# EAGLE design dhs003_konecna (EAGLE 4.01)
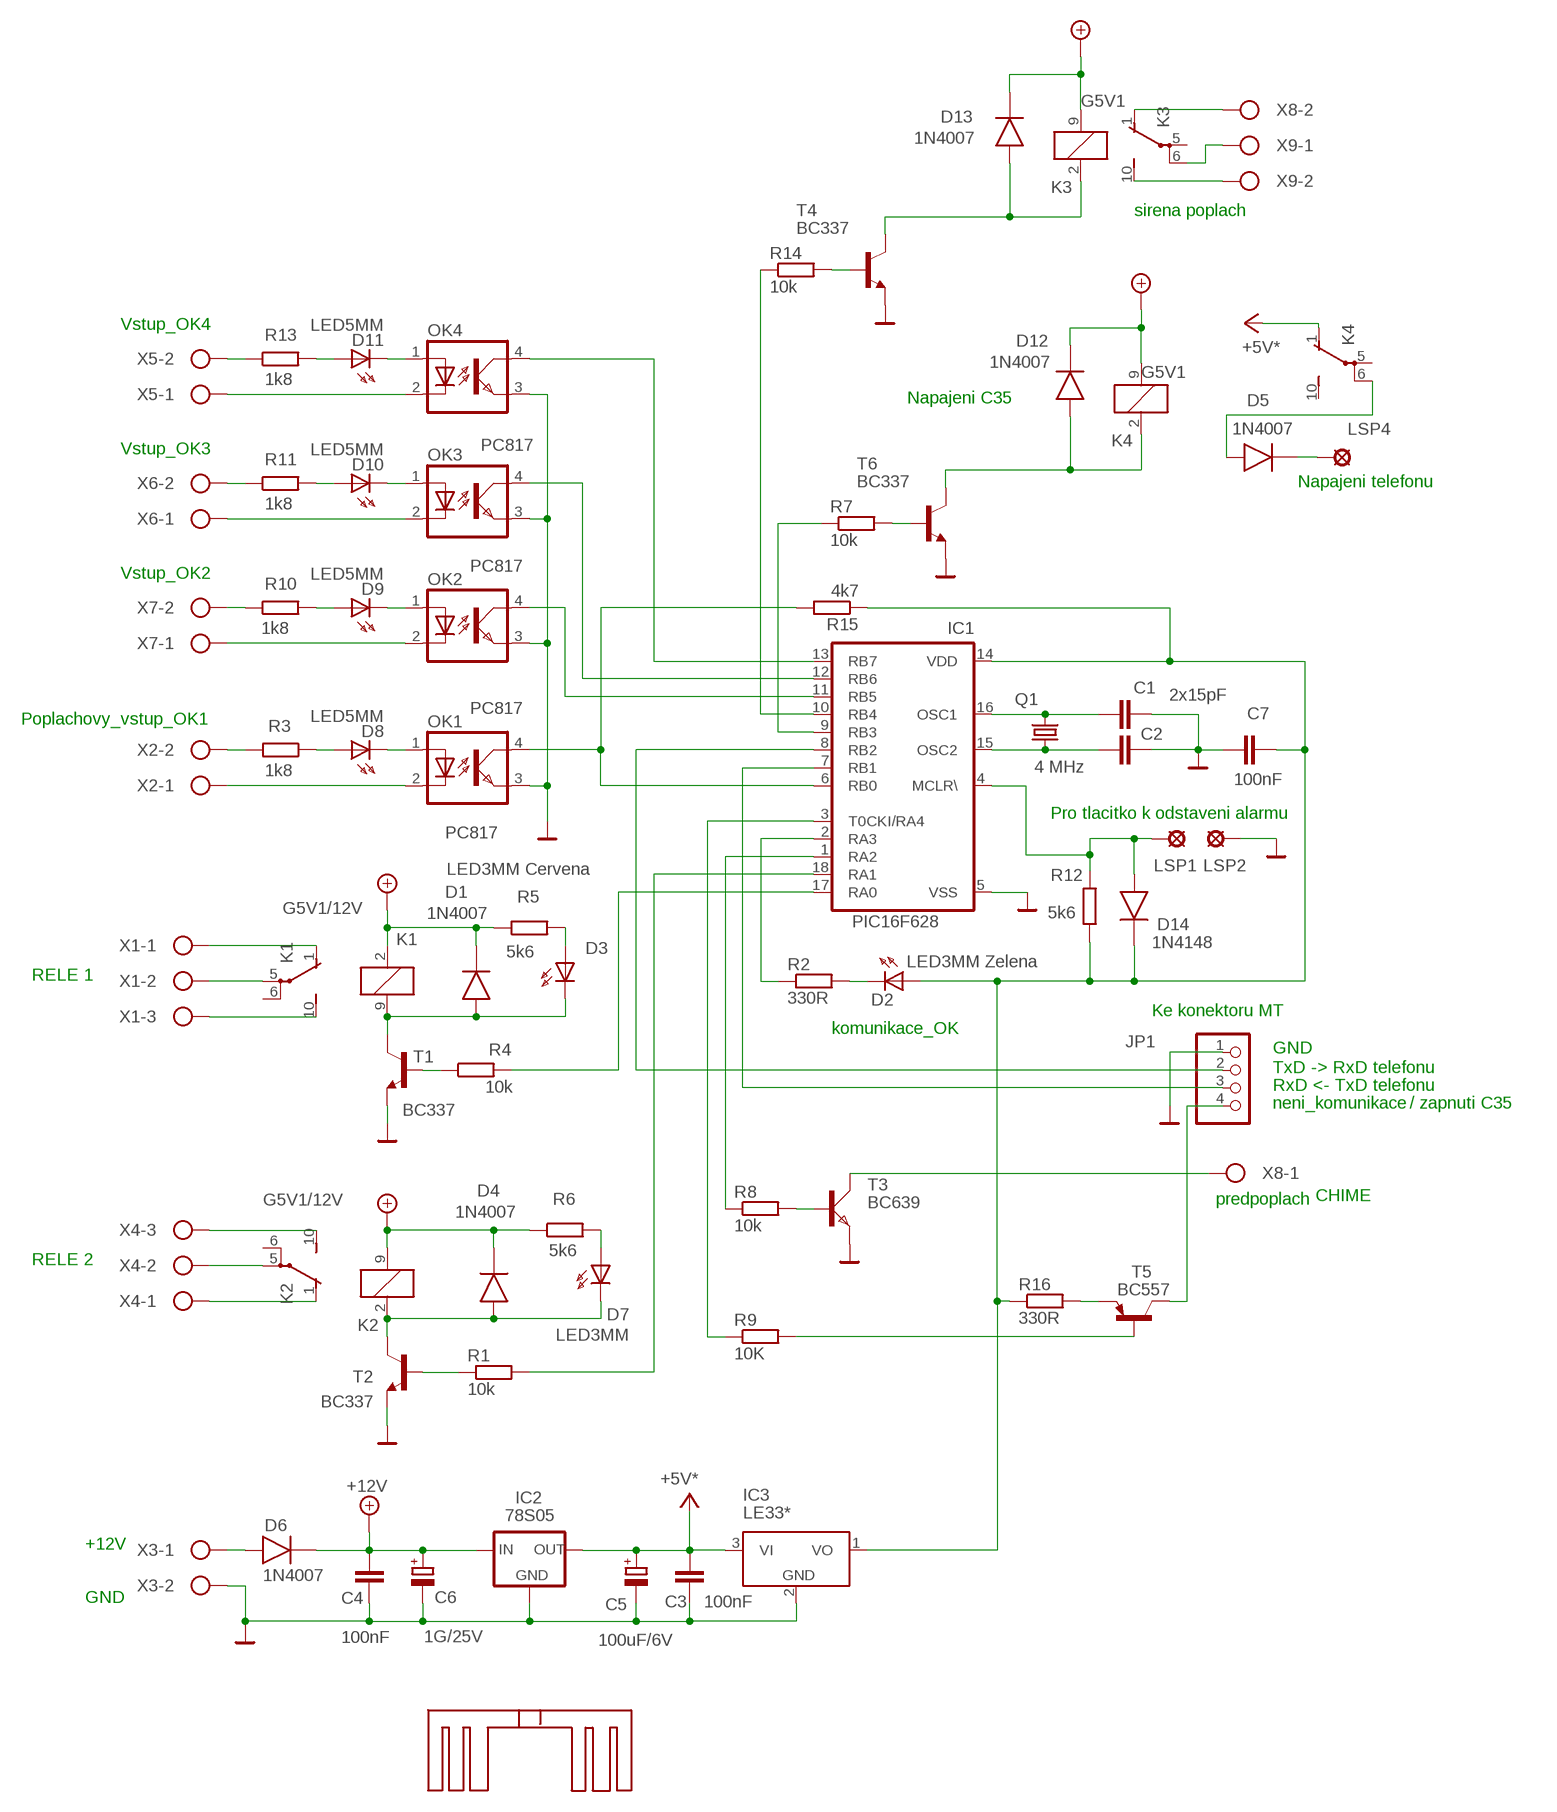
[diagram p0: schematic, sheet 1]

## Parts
C1  2x15pF  C-EU025-025X050  [C025-025X050]
C2  C-EU025-025X050  [C025-025X050]
C3  100nF  C-EU025-025X050  [C025-025X050]
C4  100nF  C-EU025-025X050  [C025-025X050]
C5  100uF/6V  CPOL-EUE2.5-7  [E2,5-7]
C6  1G/25V  CPOL-EUE5-13  [E5-13]
C7  100nF  C-EU025-025X050  [C025-025X050]
D1  1N4007  [DO41]
D2  LED3MM Zelena  LED3MM  [LED3MM]
D3  LED3MM Cervena  LED3MM  [LED3MM]
D4  1N4007  [DO41]
D5  1N4007  [DO41]
D6  1N4007  [DO41]
D7  LED3MM  [LED3MM]
D8  LED5MM  [LED5MM]
D9  LED5MM  [LED5MM]
D10  LED5MM  [LED5MM]
D11  LED5MM  [LED5MM]
D12  1N4007  [DO41]
D13  1N4007  [DO41]
D14  1N4148  [DO41]
IC1  PIC16F628  PIC16F84AP  [DIL18]
IC2  78S05  78XXS  [78XXS]
IC3  LE33*  [TO92]
JP1  PINHD-1X4  [1X04]
K1  G5V1/12V  G5V1  [G5V1]
K2  G5V1/12V  G5V1  [G5V1]
K3  G5V1  [G5V1]
K4  G5V1  [G5V1]
LSP1  LSP10  [LSP10]
LSP2  LSP10  [LSP10]
LSP4  LSP10  [LSP10]
OK1  PC817  [DIL04]
OK2  PC817  [DIL04]
OK3  PC817  [DIL04]
OK4  PC817  [DIL04]
Q1  4 MHz  HC49U-V  [HC49U-V]
R1  10k  R-EU_0207/10  [0207/10]
R2  330R  R-EU_0207/10  [0207/10]
R3  1k8  R-EU_0207/10  [0207/10]
R4  10k  R-EU_0207/10  [0207/10]
R5  5k6  R-EU_0207/10  [0207/10]
R6  5k6  R-EU_0207/10  [0207/10]
R7  10k  R-EU_0207/10  [0207/10]
R8  10k  R-EU_0207/10  [0207/10]
R9  10K  R-EU_0207/10  [0207/10]
R10  1k8  R-EU_0207/10  [0207/10]
R11  1k8  R-EU_0207/10  [0207/10]
R12  5k6  R-EU_0207/10  [0207/10]
R13  1k8  R-EU_0207/10  [0207/10]
R14  10k  R-EU_0207/10  [0207/10]
R15  4k7  R-EU_0207/10  [0207/10]
R16  330R  R-EU_0207/10  [0207/10]
RADIATOR1  V4330N*  [V4330N]
T1  BC337  [TO92]
T2  BC337  [TO92]
T3  BC639  [SOT54D]
T4  BC337  [TO92]
T5  BC557  [TO92]
T6  BC337  [TO92]
X1  AK500/3  [AK500/3]
X2  AK500/2  [AK500/2]
X3  AK500/2  [AK500/2]
X4  AK500/3  [AK500/3]
X5  AK500/2  [AK500/2]
X6  AK500/2  [AK500/2]
X7  AK500/2  [AK500/2]
X8  AK500/2  [AK500/2]
X9  AK500/2  [AK500/2]

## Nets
0V: C1.1 C2.1 C3.1 C4.1 C5.- C6.- C7.1 IC1.5(VSS) IC2.GND IC3.2(GND) JP1.1 LSP2.MP OK1.3(EMIT) OK2.3(EMIT) OK3.3(EMIT) OK4.3(EMIT) T1.1(E) T2.1(E) T3.E T4.1(E) T6.1(E) X3.2
+5V: C3.2 C5.+ IC2.OUT IC3.3(VI) K4.1(2:O) ; supply symbol labelled +5V*
+12V: C4.2 C6.+ D1.K D4.K D6.K D12.K D13.K IC2.IN K1.2 K2.9 K3.9 K4.9 R5.1 R6.1
N$1: C1.2 IC1.16(OSC1) Q1.2
N$2: C2.2 IC1.15(OSC2) Q1.1
N$3: R3.2 X2.2
N$4: OK1.2(C) X2.1
N$5: IC1.9(RB3) R7.1
N$6: K1.5(2:P) X1.2
N$7: K1.1(2:O) X1.1
N$8: IC1.17(RA0) R4.2
N$9: IC1.6(RB0) OK1.4(COL) R15.2
N$10: D4.A D7.K(C) K2.2 T2.3(C)
N$11: K2.10(2:S) X4.3
N$12: R1.1 T2.2(B)
N$13: D14.A IC1.4(MCLR\) LSP1.MP R12.2
N$14: OK2.2(C) X7.1
N$15: C7.2 D2.A D14.K IC1.14(VDD) IC3.1(VO) R12.1 R15.1 R16.1
N$16: K1.10(2:S) X1.3
N$17: IC1.2(RA3) R2.1
N$18: D2.K(C) R2.2
N$19: D1.A D3.K(C) K1.9 T1.3(C)
N$20: K2.5(2:P) X4.2
N$21: D6.A X3.1
N$22: D7.A R6.2
N$23: D3.A R5.2
N$24: R10.1 X7.2
N$25: R4.1 T1.2(B)
N$26: IC1.7(RB1) JP1.3
N$27: IC1.8(RB2) JP1.2
N$28: R11.1 X6.2
N$29: IC1.18(RA1) R1.2
N$30: K2.1(2:O) X4.1
N$31: JP1.4 T5.3(C)
N$32: IC1.1(RA2) R8.1
N$33: OK3.2(C) X6.1
N$34: D11.A R13.2
N$35: D11.K(C) OK4.1(A)
N$36: D10.A R11.2
N$37: D10.K(C) OK3.1(A)
N$38: IC1.11(RB5) OK2.4(COL)
N$39: IC1.12(RB6) OK3.4(COL)
N$40: D9.A R10.2
N$41: D9.K(C) OK2.1(A)
N$42: D8.A R3.1
N$43: OK4.2(C) X5.1
N$44: R13.1 X5.2
N$45: R8.2 T3.B
N$46: D8.K(C) OK1.1(A)
N$47: D5.K LSP4.MP
N$48: T3.C X8.1
N$49: IC1.13(RB7) OK4.4(COL)
N$50: IC1.3(T0CKI/RA4) R9.1
N$51: IC1.10(RB4) R14.1
N$52: R9.2 T5.2(B)
N$53: R14.2 T4.2(B)
N$54: D13.A K3.2 T4.3(C)
N$55: K3.6(2:P) X9.1
N$56: K3.1(2:O) X8.2
N$57: K3.10(2:S) X9.2
N$58: R16.2 T5.1(E)
N$59: D5.A K4.6(2:P)
N$61: R7.2 T6.2(B)
N$62: D12.A K4.2 T6.3(C)
Unconnected: K1.6(2:P) K2.6(2:P) K3.5(2:P) K4.5(2:P) K4.10(2:S)

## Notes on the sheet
- sirena poplach
- Vstup_OK4
- Napajeni C35
- Vstup_OK3
- Napajeni telefonu
- Vstup_OK2
- Poplachovy_vstup_OK1
- Pro tlacitko k odstaveni alarmu
- RELE 1
- Ke konektoru MT
- komunikace_OK
- GND
- TxD -> RxD telefonu
- RxD <- TxD telefonu
- neni_komunikace | / zapnuti C35
- predpoplach | CHIME
- RELE 2
- +12V
- GND

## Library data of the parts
C1-C4 C7 = rcl:C-EU: CAPACITOR, European symbol
C5 C6 = rcl:CPOL-EU: POLARIZED CAPACITOR, European symbol
D1 D4-D6 D12 D13 = GM99:1N4007
D2 D3 D7 = led:LED3MM: LED
D8-D11 = led:LED5MM: LED
D14 = GM99:1N4148
IC1 = microchip:PIC16F8*: MICROCONTROLLER 8-Bit PIC16F8X Family - CMOS Flash/EEPROM Pin Compatible : PIC16F83, PIC16CR83, PIC16F84A, PIC16CR84 see also PIC16C*
IC2 = v-reg:78XXS: VOLTAGE REGULATOR
IC3 = DH_servis:LE33
JP1 = pinhead:PINHD-1X4: PIN HEADER
K1-K4 = relay:G5V1: RELAY 1 x switch, 0.5 A/125 V AC, 1 A/24 V DC , Omron
LSP1 LSP2 LSP4 = solpad:LSP10: SOLDER PAD
OK1-OK4 = optocoupler:PC817: SHARP OPTO COUPLER
Q1 = crystal:HC49U-V: CRYSTAL
R1-R16 = rcl:R-EU_: RESISTOR, European symbol
RADIATOR1 = DH_servis:V4330N
T1 T2 T4 T6 = transistor-npn:BC337: NPN TRANSISTOR
T3 = transistor-small-signal:BC639: NPN TRANSISTOR
T5 = transistor-pnp:BC557: PNP TRANSISTOR
X1 X4 = con-ptr500:AK500/3: CONNECTOR
X2 X3 X5-X9 = con-ptr500:AK500/2: CONNECTOR

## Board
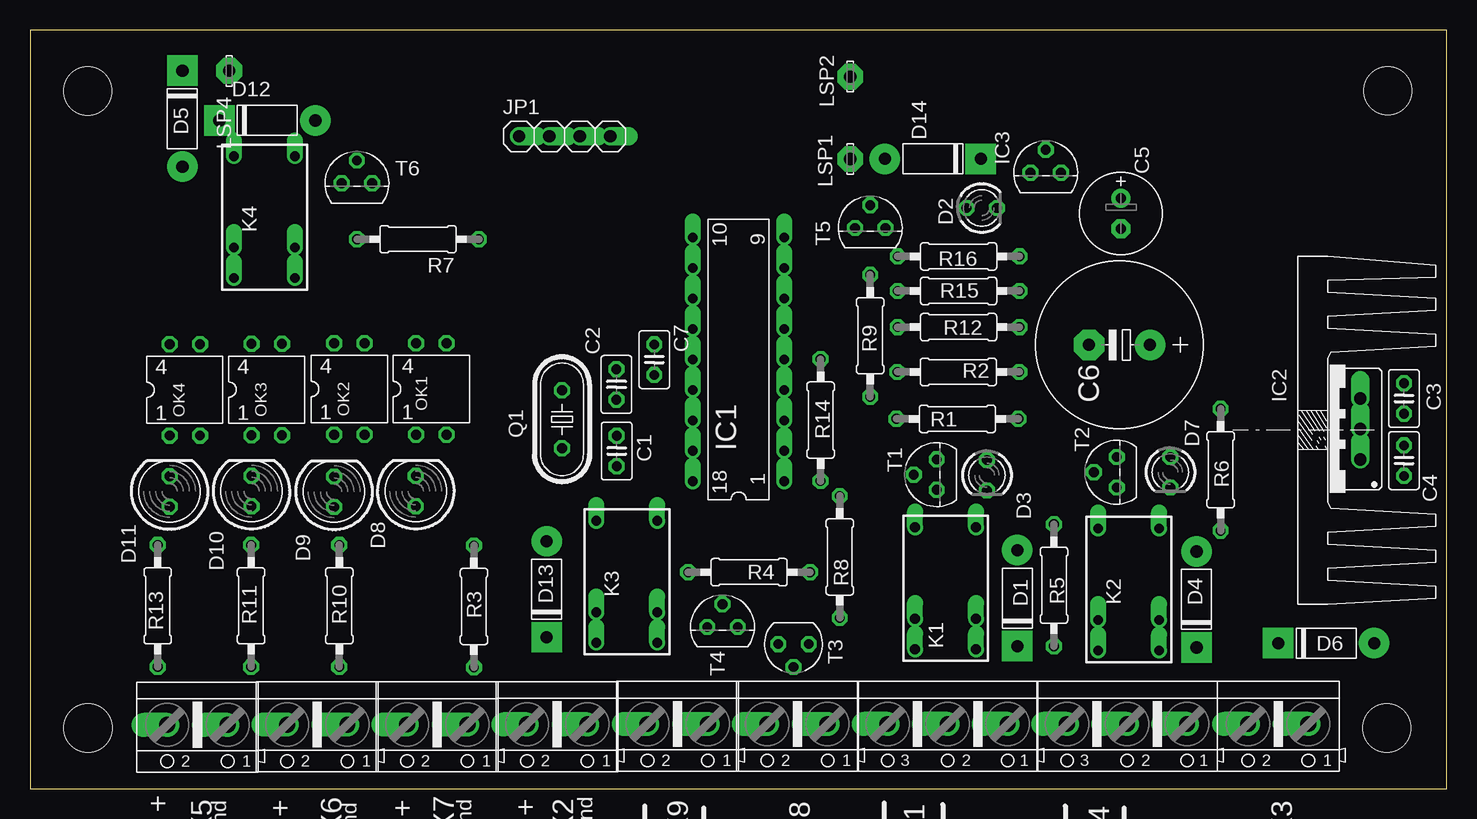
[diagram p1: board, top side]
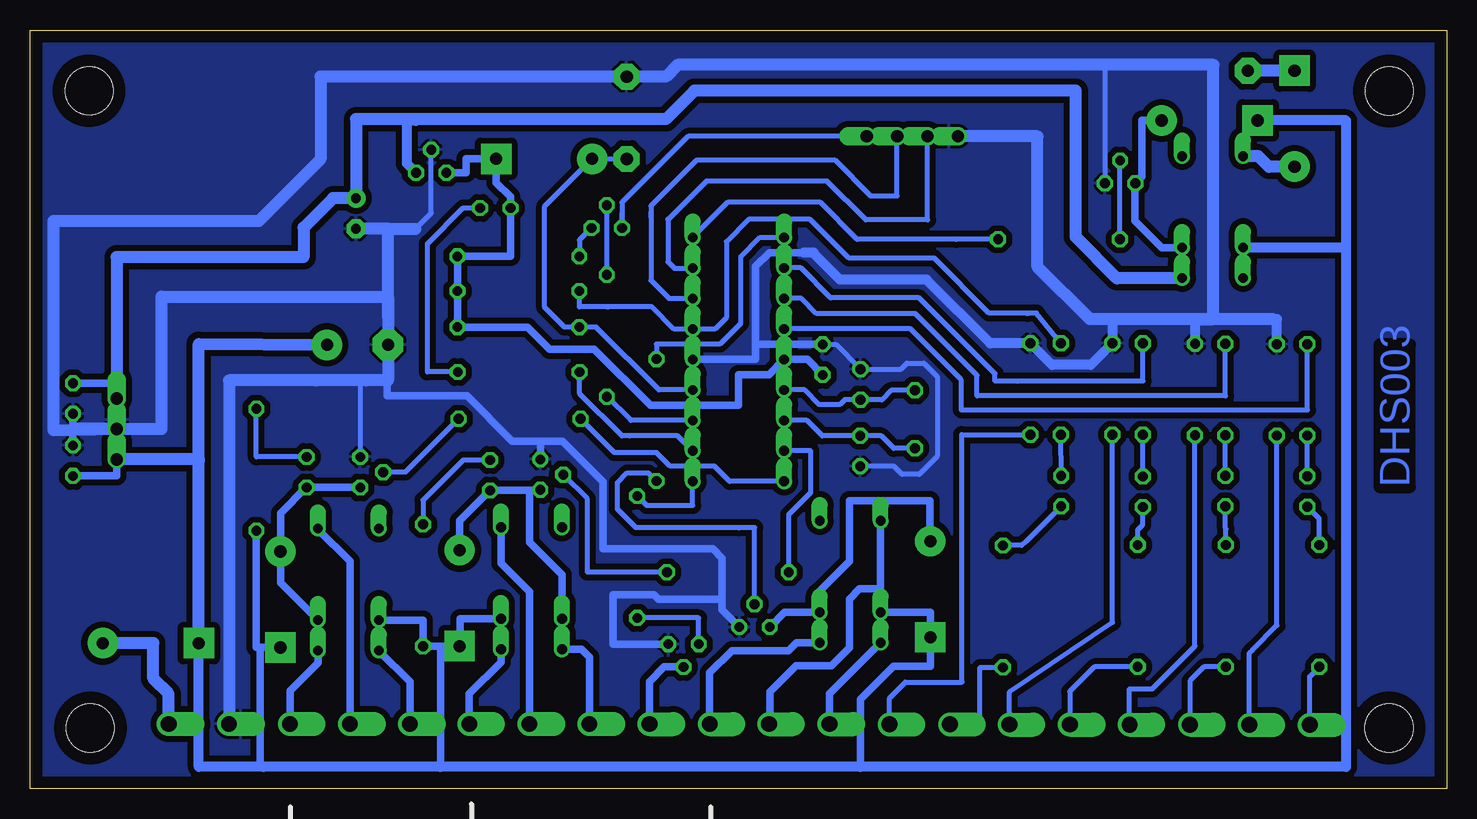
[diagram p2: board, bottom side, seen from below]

Size 118.12 x 63.21 mm. Coordinates in mm from the lower left corner, seen from the top.
Outline: 118.11,0 118.12,63.21 0,63.18 0,0 118.11,0
Copper layers used: Bottom
Holes 4 mm at 4.83,5.04 113.1,5.04 113.19,58.15 4.81,58.12

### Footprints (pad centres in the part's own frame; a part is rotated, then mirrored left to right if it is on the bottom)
C025-025X050 = drill 0.813 octagon: 1 -1.27,0; 2 1.27,0
E2,5-7 = drill 0.813 pad 1.6 round: + -1.27,0 | drill 0.813 pad 1.6 octagon: - 1.27,0
E5-13 = drill 1.016 pad 2.54 round: + -2.54,0 | drill 1.016 pad 2.54 octagon: - 2.54,0
DO41 = drill 1.016 pad 2.54 round: A 8,0 | drill 1.016 pad 2.54 square: K 0,0
LED3MM = drill 0.813 octagon: A -1.27,0; K 1.27,0
LED5MM = drill 0.813 octagon: A -1.27,0; K 1.27,0
DIL18 = drill 0.813 offset: 1 -10.16,-3.81; 2 -7.62,-3.81; 3 -5.08,-3.81; 4 -2.54,-3.81; 5 0,-3.81; 6 2.54,-3.81; 7 5.08,-3.81; 8 7.62,-3.81; 9 10.16,-3.81; 10 10.16,3.81; 11 7.62,3.81; 12 5.08,3.81; 13 2.54,3.81; 14 0,3.81; 15 -2.54,3.81; 16 -5.08,3.81; 17 -7.62,3.81; 18 -10.16,3.81
78XXS = drill 1.016 offset: GND 0,-2.54; IN -2.54,-2.54; OUT 2.54,-2.54
TO92 = drill 0.813 octagon: 1 -1.27,0; 2 0,1.905; 3 1.27,0
1X04 = drill 1.016 offset: 1 -3.81,0; 2 -1.27,0; 3 1.27,0; 4 3.81,0
G5V1 = drill 0.813 offset: 1 -5.08,-2.54; 2 -2.54,-2.54; 5 5.08,-2.54; 6 5.08,2.54; 9 -2.54,2.54; 10 -5.08,2.54
LSP10 = drill 1.016 pad 2.159 octagon: MP 0,0
DIL04 = drill 0.813 octagon: 1 -1.27,-3.81; 2 1.27,-3.81; 3 1.27,3.81; 4 -1.27,3.81
HC49U-V = drill 0.813 octagon: 1 -2.413,0; 2 2.413,0
0207/10 = drill 0.813 octagon: 1 -5.08,0; 2 5.08,0
TO92' = drill 0.813 octagon: 1 1.27,0; 2 0,1.905; 3 -1.27,0
SOT54D = drill 0.813 octagon: B 1.27,0; C 0,1.905; E -1.27,0
AK500/3 = drill 1.321 offset: 1 -5.004,0; 2 0,0; 3 5.004,0
AK500/2 = drill 1.321 offset: 1 -2.515,0; 2 2.515,0

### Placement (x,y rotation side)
C1  48.91,28.13 90 top
C2  48.88,33.68 270 top
C3  114.54,32.5 90 top
C4  114.54,27.32 270 top
C5  90.95,47.92 270 top
C6  90.82,36.98 180 top
C7  52.05,35.74 270 top
D1  82.31,11.86 90 top
D2  79.34,48.38 0 top
D3  79.77,26.11 270 top
D4  97.25,11.76 90 top
D5  12.71,59.82 270 top
D6  104.06,12.11 0 top
D7  95.06,26.36 270 top
D8  32.16,24.79 90 top
D9  25.35,24.73 90 top
D10  18.47,24.79 90 top
D11  11.64,24.76 90 top
D12  15.79,55.67 0 top
D13  43.07,12.61 90 top
D14  79.26,52.47 180 top
IC1  59.07,35.76 90 top
IC2  108.36,29.96 90 top
IC3  84.67,51.32 0 top
JP1  44.57,54.35 0 top
K1  76.32,16.68 90 top
K2  91.58,16.58 90 top
K3  49.75,17.23 90 top
K4  19.54,47.62 90 top
LSP1  68.38,52.46 90 top
LSP2  68.38,59.32 90 top
LSP4  16.61,59.81 90 top
OK1  33.45,33.29 0 top
OK2  26.62,33.29 0 top
OK3  19.74,33.24 0 top
OK4  12.91,33.22 0 top
Q1  44.35,30.77 270 top
R1  77.31,30.81 180 top
R2  77.39,34.72 0 top
R3  37.01,15.17 270 top
R4  59.95,18.03 180 top
R5  85.36,16.94 90 top
R6  99.25,26.56 90 top
R7  32.34,45.77 180 top
R8  67.5,19.3 270 top
R9  70.04,37.73 90 top
R10  25.78,15.22 90 top
R11  18.43,15.22 90 top
R12  77.41,38.45 180 top
R13  10.64,15.22 90 top
R14  65.9,30.7 270 top
R15  77.41,41.46 180 top
R16  77.41,44.34 180 top
RADIATOR1  105.68,29.87 270 top
T1  BC337  [TO92']  75.58,26.16 90 top
T2  BC337  [TO92']  90.59,26.36 90 top
T3  63.64,12.03 180 top
T4  BC337  [TO92']  57.73,13.46 0 top
T5  BC557  [TO92']  70.04,46.71 0 top
T6  BC337  [TO92']  27.25,50.43 0 top
X1  76.5,5.38 180 top
X2  43.95,5.35 180 top
X3  104.05,5.38 180 top
X4  91.45,5.38 180 top
X5  13.96,5.31 180 top
X6  23.94,5.33 180 top
X7  33.95,5.33 180 top
X8  63.98,5.38 180 top
X9  53.99,5.37 180 top

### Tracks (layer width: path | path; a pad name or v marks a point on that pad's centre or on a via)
0V
  Bottom 0.406: 90.11,34.01 90.11,34.03 90.59,34.03 T2.1 | 88.33,34.01 88.36,34.03 | C1.1 46.12,26.87 45.43,26.18 44,26.18 42.49,27.69 42.49,34.31 43.62,35.44 45.03,35.44 45.52,34.95 C2.1 50.95,37.01 C7.1 52.07,37.01 52.14,37.08 52.19,37.03 | 88.33,46.63 88.33,46.66 88.28,46.66 | IC3.2 84.68,47.95 86,46.63 | 28.52,60.3 T6.1
  Bottom 0.61: 114.52,29.96 114.52,29.93 114.55,29.93 | C4.1 114.55,28.59 114.55,29.93 | C3.1 114.55,31.23 114.55,29.93 | T3.E 69.51,12.04 69.51,16.15 66.11,16.15 65.73,15.77 60.43,15.77 60.42,15.78 60.42,19.12 | IC1.5 57.62,35.76 57.62,37.03 | 57.62,37.03 57.62,43.5 56.48,44.65 53.61,44.65 | 60.42,19.12 60.42,19.2 61.21,19.98 70.35,19.98 70.35,25.57 73.73,28.95 75.35,28.95 | T4.1 60.42,14.88 60.42,19.12 | 57.62,37.03 52.19,37.03 | T1.1 75.58,28.95 75.35,28.95 | 75.35,28.95 77.92,28.95 81.7,32.74 88.36,32.74 88.36,34.01 | 74.74,59.33 74.74,59.32 LSP2.MP
  Bottom 0.813: 94.28,34.01 94.25,34.01 | 90.11,34.01 90.01,34.01 | 88.36,34.01 88.33,34.01 88.28,34.01 | C6.- 88.28,37 88.28,36.93 | 52.95,44.65 53.61,44.65 | 52.95,44.65 52.77,44.65 | 88.28,43.91 88.28,43.99 | 88.28,46.63 88.28,46.66 | 34.8,37.1 34.76,37.14 OK1.3 32.92,35.3 29.69,35.3 OK2.3 27.89,39.11 27.88,39.11 | 52.95,44.65 52.85,44.65 50.61,42.41 43.37,42.41 38.07,37.1 34.8,37.1 | 34.8,37.1 34.79,37.1 | OK3.3 21.01,39.11 21.15,39.11 | OK4.3 14.18,39.11 14.55,39.11
  Bottom 1.016: IC2.GND 114.52,29.96 | IC2.GND 116.17,29.86 116.17,47.29 99.05,47.29 93.9,52.45 93.9,59.33 74.74,59.33 65.12,59.33 64.15,60.3 28.52,60.3 19.47,60.3 19.47,39.11 20.57,39.11 | X3.2 101.54,34.01 94.28,34.01 90.11,34.01 88.36,34.01 | C6.- 88.28,34.01 | 88.28,39.31 88.28,37 | 88.28,39.31 88.28,43.91 88.28,46.63 86,46.63 | IC2.GND 107.15,29.96 107.15,40.99 88.28,40.99 88.28,39.31 | 88.28,46.66 C5.- | 20.57,39.11 21.15,39.11 27.88,39.11 29.79,39.11 34.13,43.45 34.13,54.35 JP1.1 | 14.55,39.11 20.57,39.11
  pour Bottom (isolate 0.508): 0.32,0.5 0.32,62.48 118.18,62.99 118.18,1.01
+5V
  Bottom 0.406: 74.72,55.77 74.72,55.8 86.38,55.65 85.95,55.65 | IC3.3 85.95,51.3
  Bottom 0.61: C3.2 112.89,33.77 112.89,33.78 110.9,33.78 110.89,33.78
  Bottom 0.813: 110.9,33.78 110.9,33.75 110.91,33.75 | 90.95,49.17 C5.+ | 85.95,55.65 86.71,55.65 86.71,52.09 85.93,51.32 | 85.93,51.32 85.92,51.3 | 85.93,51.32 IC3.3
  Bottom 1.016: 110.9,33.75 IC2.OUT | 110.9,33.78 110.9,44.29 95.32,44.29 95.32,46.73 92.85,49.2 C5.+ 90.95,55.77 74.72,55.77 65.12,55.77 62.73,58.16 30.95,58.16 30.95,45.97 27.5,42.52 22.09,42.52 22.09,42.47 22.09,42.46 K4.1
+12V
  Bottom 0.305: D1.K 82.29,11.86
  Bottom 0.406: K2.9 | 98.95,11.76 D4.K | 98.67,1.8 98.95,1.8 | 83.91,11.86 84.19,11.86 | R6.1 | D6.K 104.06,12.09
  Bottom 0.61: K1.2 82.29,14.14 82.29,11.86 | D1.K 84.19,11.86 R5.1 85.36,14.04 K2.9 | IC2.IN 110.9,26.05 C4.2 | C4.2 114.55,26.05 | C4.2 | 98.95,1.8 98.95,11.76 | 83.91,1.8 83.91,11.86 | D4.K 99.25,11.76 R6.1 | K3.9 47.21,14.68 43.07,14.68 43.07,12.64 | 43.07,12.64 D13.K | 43.07,12.64 43.07,10.21 46.16,10.21 48.91,7.45 48.91,1.8
  Bottom 0.813: 104.06,27.3 104.06,27.42 | 104.06,12.09 104.06,1.8 98.67,1.8 83.91,1.8 48.91,1.8 8.4,1.8 8.4,44.83 | K4.9 8.4,45.08 8.4,44.83 | D12.K 8.4,55.67 8.4,44.83
  Bottom 1.016: 104.06,27.42 IC2.IN | D6.K 104.06,27.3 104.06,37.05 C6.+
N$1
  Bottom 0.406: Q1.2 46.11,28.35 47.15,29.4 C1.2 52.07,29.4 53.36,30.68 IC1.16
N$2
  Bottom 0.406: Q1.1 46.33,33.18 47.12,32.39 48.86,32.39 C2.2 | C2.2 | C2.2 | C2.2 50.2,32.42 50.61,32 52.32,32 53.53,33.22 IC1.15
N$3
  Bottom 0.406: R3.2 38.93,10.09 38.93,5.35 X2.2
N$4
  Bottom 0.406: 45.15,8.86 40.45,8.86 | X2.1 46.47,7.54 45.15,8.86 | 40.45,8.86 40.43,8.86 | OK1.2 40.45,29.48 40.45,8.86 | 45.15,8.86 45.17,8.86
N$5
  Bottom 0.406: IC1.9 59.96,48.84 52.24,48.84 49.17,45.77 40.91,45.77 40.9,45.78 R7.1
N$6
  Bottom 0.61: K1.5 78.86,18.76 76.47,16.38 76.47,5.48 76.39,5.41 76.42,5.5 X1.2
N$7
  Bottom 0.61: K1.1 78.86,10.54 81.5,7.89 X1.1
N$8
  Bottom 0.406: IC1.17 53.03,28.14 53.03,24.68 54.86,22.86 54.86,18 54.87,17.99 | 54.87,17.99 54.88,17.98 | R4.2 54.87,17.99
N$9
  Bottom 0.406: 62.87,38.28 62.86,38.28 | 62.87,38.28 IC1.6 62.87,38.3 62.86,38.31 62.83,38.28 61.03,38.28 60.08,39.24 60.08,45.58 58.22,47.43 53.09,47.43 49.85,44.19 42.74,44.19 38.17,39.62 35.12,39.62 | R15.2 72.33,40.13 70.04,40.13 | 35.12,39.62 34.87,39.62 | OK1.4 34.22,39.62 35.12,39.62 | 62.87,38.28 64.42,38.28 66.26,40.13 70.04,40.13 | 70.04,40.13 69.92,40.13
N$10
  Bottom 0.305: 95.09,25.09 D7.K | D4.A
  Bottom 0.61: D7.K T2.3 | 95.09,25.09 97.25,22.93 D4.A 97.25,17.16 K2.2
N$11
  Bottom 0.61: K2.10 86.45,8.91 X4.3
N$12
  Bottom 0.406: T2.2 86.83,26.36 R1.1
N$13
  Bottom 0.406: IC1.4 65.7,33.22 70.93,38.45 72.28,38.45 | R12.2 72.28,38.45 | 74.64,39.52 73.58,38.45 72.28,38.45 | 74.64,39.52 74.73,39.6 | LSP1.MP D14.A 75.23,48.51 75.23,40.1 74.64,39.52
N$14
  Bottom 0.406: OK2.2 27.88,29.48 27.88,13.84 36.47,8.05 X7.1
N$15
  Bottom 0.61: C7.2 | C7.2 | C7.2 53.33,35.76 IC1.14 56.53,34.49 59.07,34.49 59.07,31.95 66.41,31.95 71.09,36.62 74.79,36.62 76.62,38.45 R12.1 R15.1 | R15.1 82.49,41.47 | R15.1 R16.1 78.07,44.34 78.07,48.41 | D2.A 78.07,48.36 | D2.A | 78.07,48.41 D2.A | IC3.1 81.75,51.32 81.75,52.47 D14.K 79.26,50.49 78.07,49.3 78.07,48.41
N$16
  Bottom 0.61: X1.3 71.49,10.94 71.72,11.17 | 71.72,11.17 71.75,11.2 | K1.10 72.15,11.6 71.72,11.17
N$17
  Bottom 0.406: IC1.2 64.12,29.38 68.11,29.38 | R2.1 72.31,32.91 68.77,29.38 68.11,29.38 | 68.11,29.38 68.14,29.38
N$18
  Bottom 0.406: R2.2 84.98,34.72 84.98,45.41 82.01,48.38 D2.K
N$19
  Bottom 0.305: 75.58,24.84 T1.3
  Bottom 0.61: D1.A 82.31,22.3 D3.K 77.13,24.84 | K1.9 73.78,17.8 76.49,20.52 76.49,24.84 77.13,24.84 | 77.13,24.84 75.58,24.84
N$20
  Bottom 0.61: K2.5 94.12,21.61 91.46,18.94 X4.2
N$21
  Bottom 0.813: X3.1
  Bottom 1.016: D6.A 107.84,12.11 107.84,9.16 106.57,7.89 X3.1
N$22
  Bottom 0.406: R6.2 99.25,27.63 D7.A
N$23
  Bottom 0.406: D3.A 82.01,27.38 85.36,24.02 R5.2
N$24
  Bottom 0.406: R10.1 29.39,10.14 31.44,8.1 X7.2 | X7.2 | X7.2
N$25
  Bottom 0.406: T1.2 71.64,24.13 71.64,18.03 R4.1
N$26
  Bottom 0.406: JP1.3 45.84,49.37 48.02,49.37 50.99,52.34 62.58,52.34 66.36,48.56 66.36,47.64 | 66.36,47.64 66.36,48 | 66.36,47.64 66.36,42.34 64.86,40.84 IC1.7
N$27
  Bottom 0.406: IC1.8 62.88,43.35 64.41,43.35 64.94,43.89 64.94,47.42 | 62.98,49.37 64.94,47.42 | 62.98,49.37 62.58,49.78 | JP1.2 43.3,47.39 48.45,47.39 51.68,50.62 61.74,50.62 62.98,49.37 | 64.94,47.42 64.94,47.44
N$28
  Bottom 0.406: X6.2 21.43,8.96 20.26,10.13 R11.1
N$29
  Bottom 0.406: IC1.18 59.81,25.6 61.08,26.87 64.76,26.87 65.88,27.99 69.41,27.99 72.48,31.06 R1.2
N$30
  Bottom 0.61: K2.1 94.12,10.46 96.44,8.15 96.44,5.41 X4.1
N$31
  Bottom 0.406: JP1.4 63.26,54.35 68.77,48.84 T5.3 68.77,47.92
N$32
  Bottom 0.406: IC1.1 62.88,23.57 66.69,23.57 R8.1
N$33
  Bottom 0.406: OK3.2 21.01,11.87 24.58,8.3 26.46,8.3 X6.1
N$34
  Bottom 0.406: D11.A 11.65,23.49 10.65,22.48 R13.2
N$35
  Bottom 0.406: OK4.1 11.64,29.4 D11.K
N$36
  Bottom 0.406: R11.2 18.43,21.63 18.47,21.67 D10.A
N$37
  Bottom 0.406: OK3.1 18.46,29.41 D10.K
N$38
  Bottom 0.406: OK2.4 25.35,33.94 35.79,33.94 | IC1.11 53.86,43.38 51.38,40.89 44.01,40.89 37.69,34.56 37.69,33.94 35.79,33.94 | 35.79,33.94 35.77,33.94
N$39
  Bottom 0.406: OK3.4 18.47,32.71 39.18,32.71 39.18,34.43 44.33,39.57 51.78,39.57 | IC1.12 53.81,40.84 52.54,39.57 51.78,39.57 | 51.78,39.57 51.81,39.57
N$40
  Bottom 0.406: D9.A 25.37,23.47 25.37,21.94 25.39,21.94 25.78,21.55 R10.2
N$41
  Bottom 0.406: OK2.1 25.34,29.48 D9.K
N$42
  Bottom 0.406: D8.A 35.11,20.57 35.12,20.57 35.44,20.25 R3.1
N$43
  Bottom 0.406: OK4.2 14.18,13.6 16.2,11.58 | 16.2,11.58 16.22,11.55 | X5.1 16.47,11.3 16.2,11.58
N$44
  Bottom 0.406: 10.62,10.14 10.61,10.16 | 10.62,10.14 R13.1 | X5.2 11.44,9.32 10.62,10.14
N$45
  Bottom 0.406: R8.2 62.37,14.22 T3.B
N$46
  Bottom 0.406: D8.K 32.15,26.03 OK1.1
N$47
  Bottom 1.016: LSP4.MP 16.63,59.81 LSP4.MP D5.K
N$48
  Bottom 0.61: T3.C 65.27,10.13 66.49,8.91 X8.1
N$49
  Bottom 0.406: OK4.4 11.64,31.54 40.45,31.54 40.48,31.57 40.48,34.06 44.72,38.3 IC1.13
N$50
  Bottom 0.406: R9.1 70.02,32.66 68.04,30.68 IC1.3
N$51
  Bottom 0.406: IC1.10 57.27,45.92 58.87,44.32 58.87,38.78 60.62,37.03 64.41,37.03 | 64.41,37.03 64.43,37.03 | R14.1 65.9,37.03 64.41,37.03
N$52
  Bottom 0.406: R9.2 70.02,42.81 70.02,48.61 T5.2
N$53
  Bottom 0.406: 59.08,21.74 67.61,21.74 69.16,23.29 69.16,25.5 68.34,26.31 66.59,26.31 R14.2 | 59.08,21.74 58.94,21.74 | 57.73,15.34 T4.2 57.73,21.74 59.08,21.74
N$54
  Bottom 0.61: D13.A 43.11,20.61 43.11,23.97 49.8,23.97 49.8,23.26 | T4.3 55.24,14.68 52.3,14.68 K3.2 52.29,16.45 49.8,18.94 49.8,23.26 | 49.8,23.26 49.8,23.47
N$55
  Bottom 0.61: K3.6 47.21,16.63 48.96,16.63 49.83,15.77 49.83,11.72 51.3,10.24 54.26,10.24 56.46,8.05 56.46,5.3 56.51,5.36 X9.1
N$56
  Bottom 0.61: K3.1 54.23,12.15 54.91,11.48 59.61,11.48 59.61,11.5 61.46,9.64 X8.2
N$57
  Bottom 0.61: X9.2 51.48,5.25 | X9.2 | K3.10 51.48,7.88 X9.2
N$58
  Bottom 0.406: T5.1 71.34,46.71 72.33,45.72 R16.2
N$59
  Bottom 1.016: K4.6 15.73,52.7 14.85,51.81 12.74,51.81 12.73,51.82 D5.A
N$61
  Bottom 0.406: 27.25,45.77 27.26,45.77 R7.2 | 27.25,45.77 T6.2 | 27.25,45.77
N$62
  Bottom 0.406: T6.3 26,50.41 | D12.A
  Bottom 0.61: K4.2 23.76,45.08 26,47.31 26,50.41 | T6.3 25.42,51 25.42,55.67 D12.A

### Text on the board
Bottom: DHS003
tPlace: Odstav. tlacitko | GND_MT | neni_komunikace / | zapnuti_C35 | TxD -> RxD telefon | RxD <- TxD telefon | Napajeni_MT | + | + | + | + | gnd | gnd | gnd | gnd | RELE2 | GND | +12V | RELE1 | Vstup_OK4 | Vstup_OK3 | Vstup_OK2 | CHIME | Poplach | Predpoplach | Poplachovy_vstup_OK1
